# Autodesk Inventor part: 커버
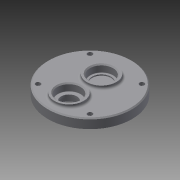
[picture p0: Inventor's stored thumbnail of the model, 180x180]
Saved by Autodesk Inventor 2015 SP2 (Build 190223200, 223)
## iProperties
Created: 2015-06
Part Number: 커버
Material: 일반
Document SubType Name: Modeling
Designer: AMC
Density: 1 g/cm^3
Appearance: 기본값
Author: AMC
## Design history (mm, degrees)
sketch "스케치1"
  geometry: C1 r 40 at (0, 0); 1 further point
  constraints: 1 centre point, 1 coincident
  dimensions: "d0" = 80 diameter of C1
extrude "돌출1" new body sketch "스케치1" distance "d1" = 9; taper "d2" = 0 deg
sketch "스케치2"
  geometry: C1 r 40 at (0, 0) reference; C2 r 14 at (0, -20); C3 r 14 at (0, 11); 1 further point
  constraints: 2 centre point, 2 vertical alignment
  dimensions: "d3" = 28 diameter of C2; "d4" = 28 diameter of C3; "d5" = 20 distance of point (0, 0) C2.centre; "d6" = 11 distance of point (0, 0) C3.centre
extrude "돌출2" join sketch "스케치2" distance "d7" = 3; taper "d8" = 0 deg
sketch "스케치3"
  geometry: C1 r 15 at (0, -20); 1 further point
  constraints: 1 centre point, 1 vertical alignment
  dimensions: "d9" = 30 diameter of C1; "d10" = 20 distance of point (0, 0) C1.centre
extrude "돌출3" join sketch "스케치3" distance "d11" = 4; taper "d12" = 0 deg
hole "구멍1" diameter "d15" = 15; stored, may be unused: countersink angle "d19" = 90 deg, drill point angle "d21" = 118 deg; dims "d13" = 10, "d14" = 10, "d16" = 6, "d17" = 22, "d18" = 7, "d20" = 8
hole "구멍2" diameter "d24" = 18; stored, may be unused: countersink angle "d28" = 90 deg, drill point angle "d30" = 0 deg; dims "d22" = 10, "d23" = 10, "d25" = 6, "d26" = 22, "d27" = 7, "d29" = 8
hole "구멍3" diameter "d33" = 22; stored, may be unused: countersink angle "d37" = 90 deg, drill point angle "d39" = 0 deg; dims "d31" = 10, "d32" = 10, "d34" = 6, "d35" = 22, "d36" = 7, "d38" = 7
sketch "스케치4" dims "d41" = 70
  geometry: L1 (0, 0)-(0, 56.769); L2 (0, 0)-(-40.657, 40.657); 2 further points
  constraints: 4 end point, 1 coincident, 1 point on line, 1 vertical, 3 other
  dimensions: "d40" = 45 deg angle of L1 L2
hole "구멍4" sketch "스케치4" at (-24.749, 24.749) diameter "d42" = 4.5; stored, may be unused: countersink angle "d46" = 90 deg, drill point angle "d48" = 0 deg; dims "d43" = 6, "d44" = 8, "d45" = 4.4, "d47" = 7
fillet "모깎기1" dims "d52" = 0.3
chamfer "모따기1" distance "d53" = 1; stored, may be unused: second distance "d54" = 2, angle "d55" = 45 deg
fillet "모깎기2" dims "d56" = 2
chamfer "모따기2" distance "d57" = 1; stored, may be unused: second distance "d58" = 2, angle "d59" = 45 deg
node "솔리드1"
pattern_circular "원형 패턴1" dims angle "d50" = 360 deg
node "투영된 루프1"
